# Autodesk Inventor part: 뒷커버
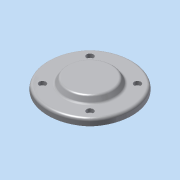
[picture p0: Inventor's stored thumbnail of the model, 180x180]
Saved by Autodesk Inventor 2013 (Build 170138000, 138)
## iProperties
Company: 한국ATC센터
Created: 2014-08
Part Number: 뒷커버
Document SubType Name: Modeling
Designer: KYOUNG IL JANG
Density: 2.71 g/cm^3
Material: 알루미늄 6061
Mass: 260.103 g
Surface Area: 228.85 cm^2
Volume: 95.9791 cm^3
Author: KYOUNG IL JANG
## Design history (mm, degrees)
sketch "스케치1"
  geometry: C1 r 30 at (0, 0) reference; A1 r 53.623 centre (0, -3.623) between (36.062, 36.062) and (-36.062, 36.062) reference; A2 r 53.623 centre (3.623, 0) between (-36.062, 36.062) and (-36.062, -36.062) reference; A3 r 53.623 centre (-3.623, 0) between (36.062, -36.062) and (36.062, 36.062) reference; A4 r 53.623 centre (0, 3.623) between (-36.062, -36.062) and (36.062, -36.062) reference; 1 further point
  node "참조9"
  node "참조14"
  node "참조15"
  node "참조16"
  node "참조17"
extrude "돌출1" new body sketch "스케치1" distance "d0" = 8; taper "d1" = 0 deg
sketch "스케치2"
  geometry: C1 r 30 at (0, 0); 1 further point
  constraints: 1 centre point, 1 coincident
  dimensions: "d2" = 60 diameter of C1
extrude "돌출2" join sketch "스케치2" distance "d3" = 7; taper "d4" = -30 deg
sketch "스케치3"
  geometry: C1 r 1.621 at (28.284, 28.284) reference; C2 r 1.621 at (-28.284, 28.284) reference; C3 r 1.621 at (-28.284, -28.284) reference; C4 r 1.621 at (28.284, -28.284) reference; 1 further point
hole "구멍2" sketch "스케치3" at (-28.284, -28.284), (-28.284, 28.284), (28.284, 28.284), (28.284, -28.284) diameter "d14" = 4.5; stored, may be unused: countersink angle "d18" = 90 deg, drill point angle "d20" = 118 deg; dims "d15" = 6, "d16" = 8, "d17" = 4.4, "d19" = 20
extrude "돌출3" join sketch "스케치1" distance "d21" = 12; taper "d22" = 0 deg
hole "구멍3" diameter "d25" = 30; stored, may be unused: countersink angle "d29" = 90 deg, drill point angle "d31" = 0 deg; dims "d23" = 10, "d24" = 10, "d26" = 6, "d27" = 40, "d28" = 12, "d30" = 15
fillet "모깎기1" dims "d32" = 3, "d33" = 0.3
chamfer "모따기1" distance "d34" = 1; stored, may be unused: second distance "d35" = 2, angle "d36" = 45 deg
node "솔리드1"
node "참조18"
node "참조19"
node "참조20"
node "참조21"
